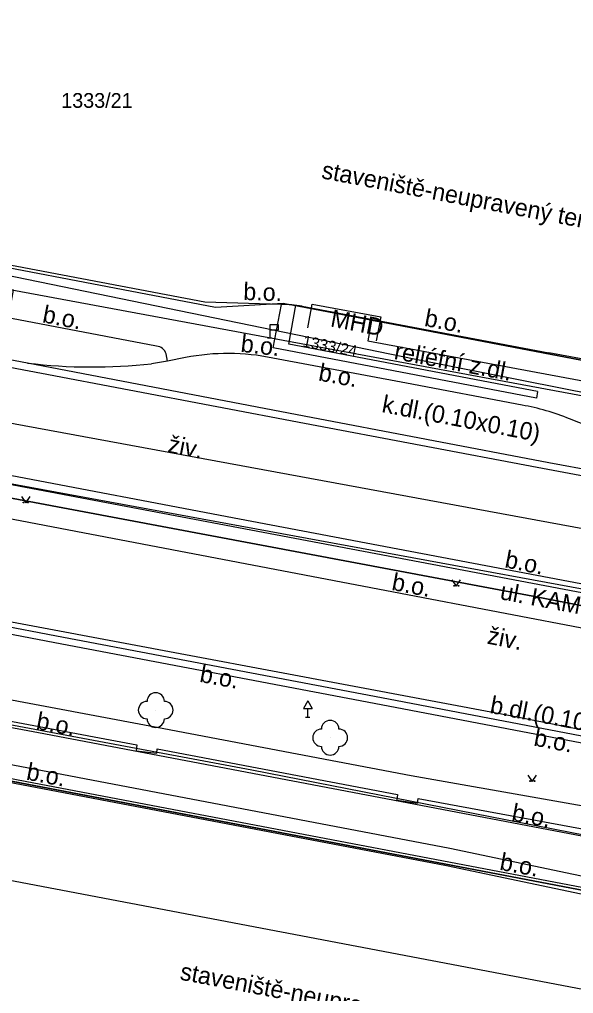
# Model space of a CAD drawing. Extents: x -601602 to -600882, y -1162594 to -1161950.
# Drawn here: x -601387.9 to -601356, y -1162336.4 to -1162280.3 of the extents above; entities that cross this region are included whole.
import ezdxf

# ---------------------------------------------------------------- set-up
doc = ezdxf.new("R2010")
doc.units = 0
for name, color, linetype in [('KN_Hranice parcel', 7, 'Continuous'), ('KN_Parcelní čísla', 7, 'Continuous'), ('KN_Věcná břemena k části', 7, 'Continuous'), ('VRSTVA 1', 7, 'Continuous'), ('Vrstva 13', 7, 'Continuous'), ('Vrstva 14', 7, 'Continuous'), ('Vrstva 15 (Construction)', 7, 'Continuous'), ('Vrstva 16', 7, 'Continuous'), ('VRSTVA 3', 7, 'Continuous'), ('Vrstva 6', 7, 'Continuous'), ('Vrstva 8', 7, 'Continuous')]:
    doc.layers.add(name, color=color, linetype=linetype)

msp = doc.modelspace()

# ---------------------------------------------------------------- linework, layer by layer
at = {"layer": 'KN_Hranice parcel'}
for p, q in [((-601418.98, -1162290.19), (-601349.03, -1162303.17)), ((-601340.99, -1162333.19), (-601393.45, -1162323.18))]:
    msp.add_line(p, q, dxfattribs=at)
for points in [[(-601346.72, -1162315.75), (-601358.39, -1162313.5), (-601389.94, -1162307.57), (-601406.17, -1162304.44), (-601488.01, -1162288.67)], [(-601414.77, -1162289.58), (-601376.64, -1162296.86), (-601372.76, -1162296.64), (-601349.26, -1162301.12)], [(-601391.58, -1162314.37), (-601359.88, -1162320.33), (-601349.94, -1162322.27), (-601329.55, -1162326.15)], [(-601345.55, -1162338.03), (-601346.43, -1162337.86), (-601465.12, -1162315.27)]]:
    msp.add_lwpolyline(points, dxfattribs=at)
at = {"layer": 'KN_Věcná břemena k části'}
for points in [[(-601319.34, -1162319.73), (-601318.72, -1162316.39), (-601326.64, -1162314.93), (-601327.32, -1162314.81), (-601389.66, -1162303.33), (-601388.27, -1162295.89), (-601391.51, -1162295.29), (-601392.9, -1162302.72), (-601436.53, -1162294.41), (-601483.89, -1162284.37), (-601487.52, -1162280.9), (-601487.57, -1162281.75), (-601487.71, -1162283.88), (-601487.81, -1162285.47), (-601486.76, -1162286.48), (-601487.31, -1162288.8), (-601483.87, -1162289.47), (-601483.5, -1162287.92), (-601437.21, -1162297.75), (-601391.91, -1162306.37), (-601327.93, -1162318.15), (-601327.24, -1162318.27)], [(-601349.13, -1162302.29), (-601349.26, -1162301.12), (-601365.47, -1162298.03), (-601367.67, -1162297.62), (-601367.89, -1162298.8)], [(-601340.46, -1162325.49), (-601340.18, -1162324.13), (-601343.62, -1162323.47), (-601343.9, -1162324.81), (-601344.69, -1162329.03), (-601344.71, -1162329.07), (-601344.93, -1162329.2), (-601345.26, -1162329.25), (-601374.56, -1162323.51), (-601392.8, -1162320.1), (-601410.16, -1162316.86), (-601424.81, -1162314.13), (-601488.87, -1162302.17), (-601488.95, -1162303.71), (-601489.01, -1162304.59), (-601465.65, -1162309.39), (-601426.59, -1162316.85), (-601404.54, -1162321.04), (-601393.45, -1162323.18), (-601344.64, -1162332.49), (-601343.79, -1162332.38), (-601342.39, -1162331.51), (-601341.29, -1162329.93)], [(-601340.7, -1162333.75), (-601340.99, -1162333.19), (-601393.45, -1162323.18), (-601404.54, -1162321.04), (-601426.59, -1162316.85), (-601465.65, -1162309.39), (-601482.83, -1162306.11), (-601485.38, -1162306.86), (-601486.35, -1162307), (-601489.12, -1162306.51), (-601489.17, -1162307.52), (-601486.36, -1162308.02), (-601485.17, -1162307.84), (-601482.92, -1162307.18), (-601482.38, -1162307.02), (-601480.64, -1162307.08), (-601432.85, -1162316.22), (-601430.16, -1162316.73), (-601428.76, -1162316.98), (-601393.64, -1162323.22), (-601393.47, -1162323.26), (-601363.36, -1162329), (-601345.3, -1162332.79)]]:
    msp.add_lwpolyline(points, close=True, dxfattribs=at)
for points in [[(-601488.01, -1162288.67), (-601406.17, -1162304.44), (-601389.94, -1162307.57), (-601358.39, -1162313.5), (-601346.72, -1162315.75), (-601335.66, -1162317.85), (-601335.54, -1162317.35), (-601341.73, -1162315.93), (-601340.34, -1162308.62), (-601335.82, -1162309.28), (-601333.32, -1162306.08), (-601334.65, -1162305.84), (-601335.66, -1162307.13), (-601335.84, -1162305.61), (-601337.08, -1162305.38), (-601336.77, -1162307.94), (-601341.3, -1162307.26), (-601342.91, -1162315.69), (-601475.53, -1162290.59)], [(-601330.48, -1162345.09), (-601335.94, -1162335.01), (-601336.82, -1162334.08), (-601338.18, -1162333.25), (-601344.57, -1162331.92), (-601343.49, -1162328.19), (-601342.51, -1162323.68), (-601343.49, -1162323.5), (-601344.46, -1162327.95), (-601345.55, -1162331.71), (-601363.17, -1162328.02), (-601393.26, -1162322.28), (-601393.46, -1162322.24), (-601425.07, -1162316.62), (-601429.98, -1162315.75), (-601480.53, -1162306.08)], [(-601465.65, -1162309.39), (-601426.59, -1162316.85), (-601404.54, -1162321.04), (-601393.45, -1162323.18), (-601340.99, -1162333.19), (-601340.7, -1162333.75), (-601338.55, -1162334.19), (-601337.46, -1162334.87), (-601336.76, -1162335.6), (-601331.74, -1162344.87)], [(-601349.83, -1162326.58), (-601365.39, -1162323.84), (-601380.42, -1162320.97), (-601392.5, -1162318.72)], [(-601392.75, -1162319.89), (-601381.18, -1162322.05), (-601381.22, -1162322.4), (-601380.02, -1162322.52), (-601380, -1162322.27), (-601366.18, -1162324.91), (-601366.22, -1162325.24), (-601365.02, -1162325.4), (-601364.98, -1162325.14), (-601350.86, -1162327.75)]]:
    msp.add_lwpolyline(points, dxfattribs=at)
at = {"layer": 'VRSTVA 1'}
msp.add_lwpolyline([(-601331.31, -1162306.58), (-601332.3, -1162306.37), (-601334.05, -1162306.03), (-601365.21, -1162299.85), (-601405.05, -1162291.66), (-601414.46, -1162290.57), (-601424.01, -1162291.3), (-601452.18, -1162285.72), (-601481.36, -1162280.32), (-601487.9, -1162279.02), (-601506.8, -1162275.08), (-601511.71, -1162274.13), (-601531.56, -1162268.63), (-601534.84, -1162286.8), (-601535.95, -1162290.68)], dxfattribs=at)
at = {"layer": 'Vrstva 13'}
for p, q in [((-601377.27, -1162296.58), (-601405.03, -1162291.29)), ((-601380.04, -1162299.1), (-601404.65, -1162294.41)), ((-601387.46, -1162300.08), (-601406.95, -1162296.41)), ((-601372.86, -1162296.71), (-601377.27, -1162296.58)), ((-601373.33, -1162299.21), (-601372.86, -1162296.71)), ((-601372.42, -1162299), (-601372.02, -1162296.75)), ((-601386.66, -1162300.68), (-601406.99, -1162296.79)), ((-601371.67, -1162296.8), (-601357.47, -1162299.49)), ((-601358.11, -1162301.71), (-601372.42, -1162299)), ((-601379.41, -1162299.96), (-601379.49, -1162299.55)), ((-601358.18, -1162302.1), (-601373.33, -1162299.21)), ((-601340.58, -1162302.66), (-601357.47, -1162299.49)), ((-601371.55, -1162303.14), (-601387.46, -1162300.08)), ((-601379.41, -1162299.96), (-601380.33, -1162300.12)), ((-601378.38, -1162299.76), (-601379.41, -1162299.96)), ((-601365.66, -1162301.24), (-601373.35, -1162299.79)), ((-601371.52, -1162303.55), (-601386.66, -1162300.68)), ((-601359.01, -1162302.5), (-601365.66, -1162301.24)), ((-601358.11, -1162301.71), (-601358.18, -1162302.1)), ((-601357.46, -1162305.82), (-601371.55, -1162303.14)), ((-601345.64, -1162307.5), (-601356.27, -1162303.29)), ((-601358.13, -1162306.09), (-601371.52, -1162303.55)), ((-601398.86, -1162304.55), (-601375.26, -1162309.05)), ((-601342.86, -1162308.98), (-601358.13, -1162306.09)), ((-601342.8, -1162308.53), (-601357.46, -1162305.82)), ((-601384.68, -1162309.77), (-601400.73, -1162306.71)), ((-601375.26, -1162309.05), (-601355.63, -1162312.77)), ((-601366.01, -1162313.34), (-601384.68, -1162309.77)), ((-601385.8, -1162315.79), (-601401.9, -1162312.72)), ((-601385.89, -1162316.18), (-601402, -1162313.09)), ((-601347.78, -1162316.81), (-601366.01, -1162313.34)), ((-601367.09, -1162319.35), (-601385.8, -1162315.79)), ((-601367.12, -1162319.75), (-601385.89, -1162316.18)), ((-601386.84, -1162321.36), (-601403.1, -1162318.26)), ((-601349.52, -1162323.1), (-601367.12, -1162319.75)), ((-601349.37, -1162322.73), (-601367.09, -1162319.35)), ((-601387.11, -1162324.26), (-601403.62, -1162321.11)), ((-601367.96, -1162324.95), (-601386.84, -1162321.36)), ((-601368.37, -1162327.82), (-601387.11, -1162324.26)), ((-601350.29, -1162328.31), (-601367.96, -1162324.95)), ((-601350.87, -1162331.15), (-601368.37, -1162327.82))]:
    msp.add_line(p, q, dxfattribs=at)
for centre, radius, start, end in [((-601372.741, -1162303.045), 6.336, 80.2711, 91.0787), ((-601380.119, -1162299.758), 0.663, 18.2925, 83.1287), ((-601375.94, -1162312.364), 12.838, 78.3606, 100.956), ((-601383.721, -1162269.131), 31.174, 263.1119, 276.2453), ((-601361.205, -1162315.258), 12.946, 67.5933, 80.2399)]:
    msp.add_arc(centre, radius, start, end, dxfattribs=at)
at = {"layer": 'Vrstva 14'}
msp.add_lwpolyline([(-601358.672, -1162323.785), (-601358.422, -1162324.16), (-601358.172, -1162323.785)], dxfattribs=at)
for centre, radius in [((-601380.09, -1162320.05), 0.0005), ((-601370.05, -1162321.64), 0.0005), ((-601358.547, -1162324.135), 0.025), ((-601358.547, -1162324.135), 0.025), ((-601358.297, -1162324.135), 0.025), ((-601358.297, -1162324.135), 0.025)]:
    msp.add_circle(centre, radius, dxfattribs=at)
for centre, start, end in [((-601380.09, -1162319.55), 0, 180), ((-601380.59, -1162320.05), 90, 270), ((-601379.59, -1162320.05), 270, 90), ((-601380.09, -1162320.55), 180, 360), ((-601370.05, -1162321.14), 0, 180), ((-601370.55, -1162321.64), 90, 270), ((-601369.55, -1162321.64), 270, 90), ((-601370.05, -1162322.14), 180, 360)]:
    msp.add_arc(centre, 0.5, start, end, dxfattribs=at)
at = {"layer": 'VRSTVA 3'}
for points in [[(-601387.818, -1162307.749), (-601387.568, -1162308.124), (-601387.318, -1162307.749)], [(-601363.043, -1162312.545), (-601362.793, -1162312.92), (-601362.543, -1162312.545)]]:
    msp.add_lwpolyline(points, dxfattribs=at)
for centre in [(-601387.693, -1162308.099), (-601387.443, -1162308.099), (-601362.918, -1162312.895), (-601362.668, -1162312.895)]:
    msp.add_circle(centre, 0.025, dxfattribs=at)
at = {"layer": 'Vrstva 6'}
for p, q in [((-601371.337, -1162298.052), (-601371.08, -1162296.68)), ((-601371.08, -1162296.68), (-601367.13, -1162297.42)), ((-601367.13, -1162297.42), (-601367.4, -1162298.79))]:
    msp.add_line(p, q, dxfattribs=at)
at = {"layer": 'Vrstva 8'}
for p, q in [((-601373.53, -1162298.17), (-601373.53, -1162298.62)), ((-601373.655, -1162298.62), (-601373.405, -1162298.62)), ((-601371.34, -1162319.517), (-601371.59, -1162319.95)), ((-601371.34, -1162319.517), (-601371.09, -1162319.95)), ((-601371.59, -1162319.95), (-601371.09, -1162319.95)), ((-601371.34, -1162320.45), (-601371.34, -1162319.95)), ((-601371.465, -1162320.45), (-601371.215, -1162320.45))]:
    msp.add_line(p, q, dxfattribs=at)
msp.add_lwpolyline([(-601373.53, -1162298.17), (-601373.03, -1162298.17), (-601373.03, -1162297.87), (-601373.53, -1162297.87)], close=True, dxfattribs=at)

# ---------------------------------------------------------------- texts
at = {"layer": 'KN_Parcelní čísla'}
msp.add_text('1333/21', height=0.85, dxfattribs=at).set_placement((-601385.527, -1162285.39))
msp.add_text('1333/24', height=0.6535, rotation=349, dxfattribs=at).set_placement((-601371.674, -1162299.121))
at = {"layer": 'Vrstva 15 (Construction)'}
msp.add_text('ul. KAMENICE', height=1, rotation=349.2405, dxfattribs=at).set_placement((-601360.322, -1162313.66))
at = {"layer": 'Vrstva 16'}
for s, rotation, p in [('staveniště-neupravený terén', 349.2216, (-601370.595, -1162289.436)), ('b.o.', 358.3308, (-601375.059, -1162296.449)), ('b.o.', 348.9478, (-601386.655, -1162297.723)), ('MHD', 349.1687, (-601370.083, -1162297.966)), ('b.o.', 349.185, (-601364.673, -1162297.935)), ('b.o.', 353.5132, (-601375.233, -1162299.426)), ('reliéfní z.dl.', 349.2777, (-601366.416, -1162299.836)), ('b.o.', 349.6414, (-601370.77, -1162301.072)), ('k.dl.(0.10x0.10)', 349.2295, (-601367.124, -1162302.893)), ('živ.', 348.7361, (-601379.445, -1162305.205)), ('b.o.', 348.9489, (-601360.05, -1162311.829)), ('b.o.', 349.2606, (-601366.555, -1162313.128)), ('živ.', 348.7361, (-601361.06, -1162316.216)), ('b.o.', 349.4434, (-601377.608, -1162318.417)), ('b.dl.(0.10x0.20)', 349.2283, (-601360.904, -1162320.209)), ('b.o.', 349.4434, (-601387.012, -1162321.129)), ('b.o.', 349.4434, (-601358.381, -1162322.089)), ('b.o.', 349.4434, (-601387.579, -1162324.047)), ('b.o.', 349.4434, (-601359.652, -1162326.401)), ('b.o.', 349.4434, (-601360.341, -1162329.233)), ('staveniště-neupravený terén', 349.2216, (-601378.74, -1162335.553))]:
    msp.add_text(s, height=1, rotation=rotation, dxfattribs=at).set_placement(p)

doc.saveas('drawing.dxf')
